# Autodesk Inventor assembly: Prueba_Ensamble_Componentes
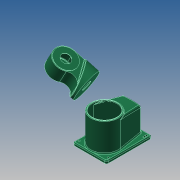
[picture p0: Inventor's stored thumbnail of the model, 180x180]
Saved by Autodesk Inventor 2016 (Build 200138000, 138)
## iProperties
Created: 2015-10
Part Number: Prueba_Ensamble_Componentes
Document SubType Name: Assembly
Designer: julian.chica
Mass: 551.13 g
Surface Area: 5528.76 cm^2
Volume: 551.13 cm^3
Density: 1 g/cm^3
Author: julian.chica
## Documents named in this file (3)
- C:\Test ExamProfessor 2015\Prueba_Ensamble_Componentes.iam
- C:\Test ExamProfessor 2015\Robot-Base-Model-A.ipt
- C:\Test ExamProfessor 2015\Robot-Axis1-2.ipt
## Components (2 placed, 2 different names)
1. Robot-Base-Model-A:1
2. Robot-Axis1-2:1
